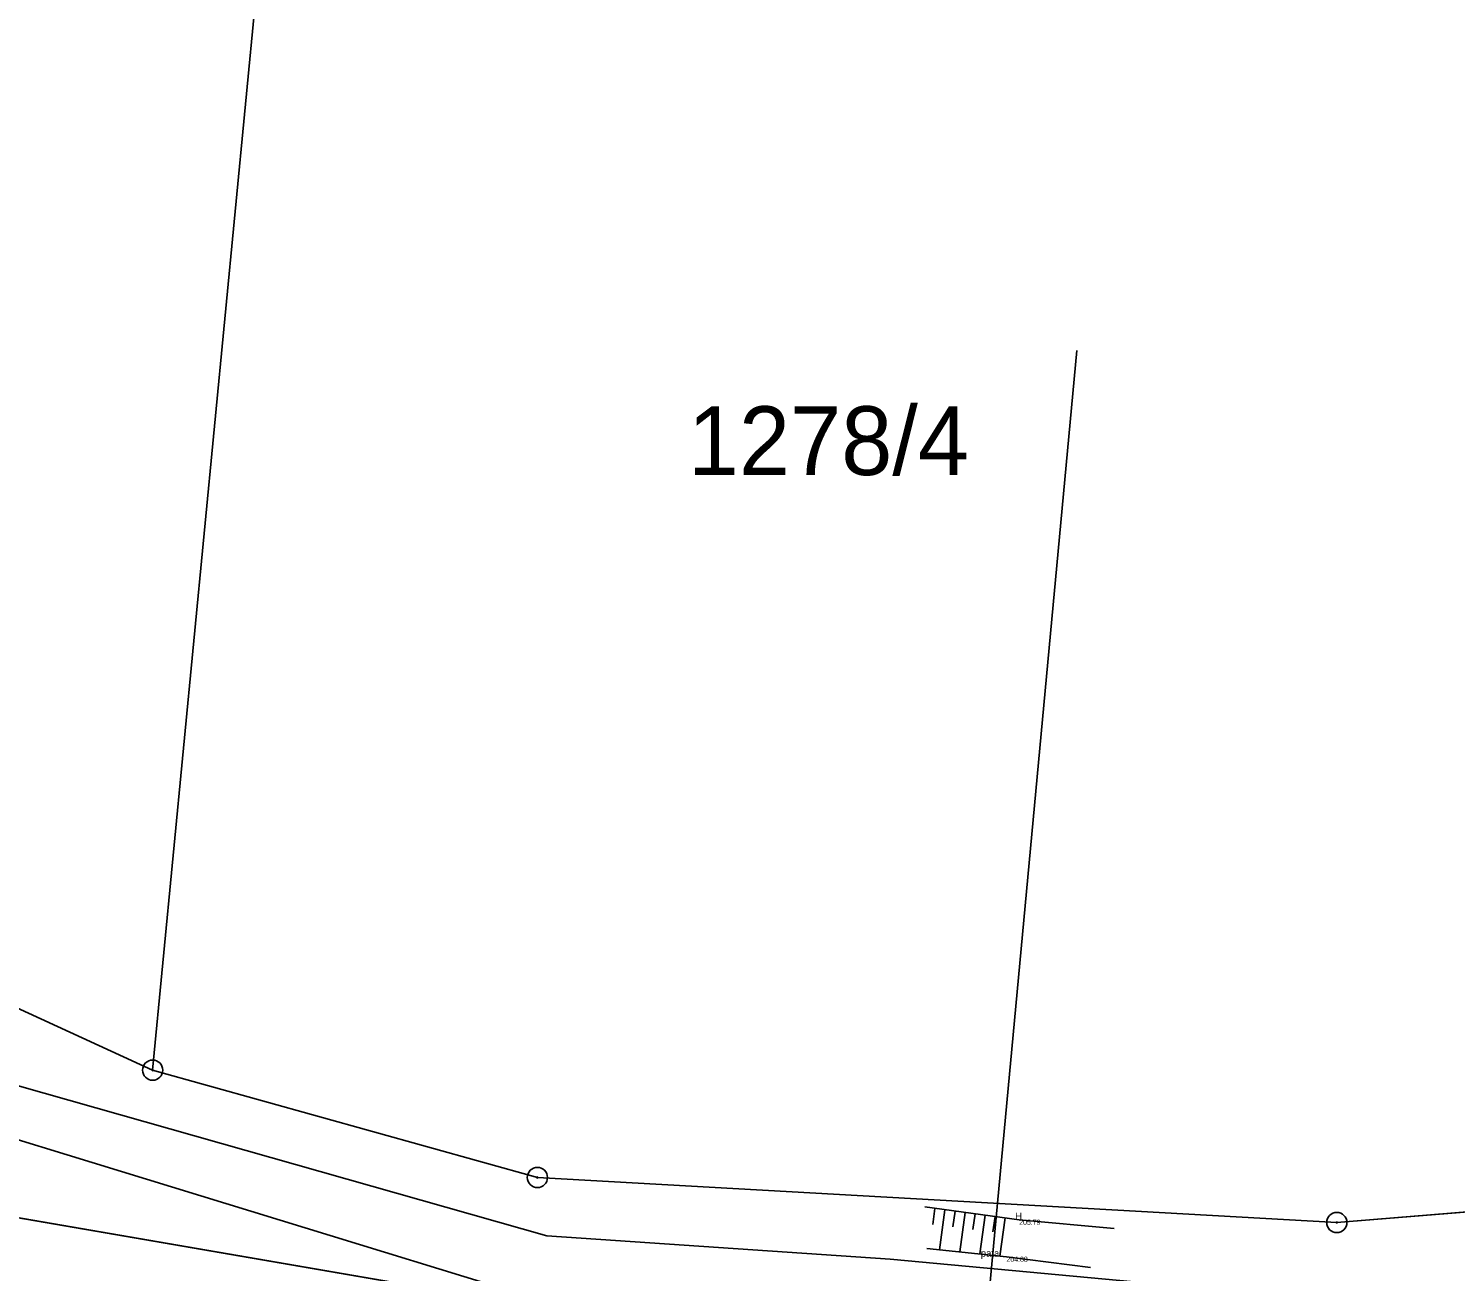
# Model space of a CAD drawing. Extents: x -537341 to -532984, y -1143469 to -1141314.
# Drawn here: x -535152.1 to -535081.5, y -1142823.6 to -1142762.2 of the extents above; entities that cross this region are included whole.
import ezdxf

# ---------------------------------------------------------------- set-up
doc = ezdxf.new("R2010")
doc.units = 0
for name, color, linetype in [('Hranice parcel', 7, 'Continuous'), ('parcelní_č_2000', 7, 'Continuous'), ('u_obec_Horní_Moš', 7, 'Continuous'), ('u_osa_toku', 7, 'Continuous'), ('u_pozemkový_úřad', 7, 'Continuous'), ('u_pricne', 7, 'Continuous'), ('U_SOUKROMÉ', 7, 'Continuous'), ('Značky bodu BP', 7, 'Continuous'), ('ˇ1', 7, 'Continuous'), ('ˇ12', 7, 'Continuous'), ('ˇ13', 7, 'Continuous'), ('ˇ18', 7, 'Continuous'), ('ˇ3', 7, 'Continuous')]:
    doc.layers.add(name, color=color, linetype=linetype)

msp = doc.modelspace()

# ---------------------------------------------------------------- linework, layer by layer
at = {"layer": 'Hranice parcel'}
msp.add_line((-535145.96, -1142813.69), (-535134.247, -1142691.905), dxfattribs=at)
for points in [[(-535145.96, -1142813.69), (-535169.91, -1142802.7), (-535192.81, -1142789.83), (-535204.32, -1142784.26), (-535252.88, -1142770.83), (-535272.1, -1142771.17), (-535285.84, -1142775.59)], [(-535405.82, -1142867.75), (-535312.5, -1142806.96), (-535286.28, -1142782.06), (-535276.92, -1142778.23), (-535253.61, -1142777.35), (-535211.35, -1142788.27), (-535160.74, -1142814.65), (-535123.95, -1142825.93)], [(-535123.95, -1142825.93), (-535162.05, -1142819.37), (-535213.73, -1142796.84), (-535250.05, -1142784.79), (-535271.96, -1142788.49), (-535310.42, -1142811.28), (-535403.84, -1142870.01)], [(-535070.92, -1142819.89), (-535087.39, -1142821.23), (-535126.93, -1142819), (-535145.96, -1142813.69)]]:
    msp.add_lwpolyline(points, dxfattribs=at)
at = {"layer": 'u_obec_Horní_Moš'}
for points in [[(-535145.96, -1142813.69), (-535169.91, -1142802.7), (-535192.81, -1142789.83), (-535204.32, -1142784.26), (-535252.88, -1142770.83), (-535272.1, -1142771.17), (-535285.84, -1142775.59)], [(-535405.82, -1142867.75), (-535312.5, -1142806.96), (-535286.28, -1142782.06), (-535276.92, -1142778.23), (-535253.61, -1142777.35), (-535211.35, -1142788.27), (-535160.74, -1142814.65), (-535123.95, -1142825.93)], [(-535070.92, -1142819.89), (-535087.39, -1142821.23), (-535126.93, -1142819), (-535145.96, -1142813.69)]]:
    msp.add_lwpolyline(points, dxfattribs=at)
at = {"layer": 'u_osa_toku'}
msp.add_lwpolyline([(-535260.582, -1142774.976), (-535252.427, -1142775.194), (-535238.285, -1142777.932), (-535206.255, -1142787.029), (-535160.007, -1142812.372), (-535126.471, -1142821.884), (-535109.48, -1142823.039), (-535088.356, -1142825.002), (-535065.679, -1142822.408), (-535055.402, -1142821.914), (-535044.659, -1142821.993), (-534991.553, -1142827.025), (-534966.505, -1142828.778), (-534955.891, -1142830.192), (-534942.11, -1142833.833), (-534919.335, -1142841.154), (-534875.463, -1142853.452), (-534792.866, -1142883.369), (-534735.912, -1142905.174), (-534690.752, -1142922.463), (-534647.384, -1142937.62), (-534638.575, -1142939.364), (-534623.017, -1142940.808), (-534607.282, -1142942.643)], dxfattribs=at)
at = {"layer": 'u_pozemkový_úřad'}
msp.add_line((-535123.95, -1142825.93), (-535162.05, -1142819.37), dxfattribs=at)
for points in [[(-535403.84, -1142870.01), (-535310.42, -1142811.28), (-535271.96, -1142788.49), (-535250.05, -1142784.79), (-535213.73, -1142796.84), (-535162.05, -1142819.37), (-535123.95, -1142825.93)], [(-535123.95, -1142825.93), (-535160.74, -1142814.65), (-535211.35, -1142788.27)]]:
    msp.add_lwpolyline(points, dxfattribs=at)
at = {"layer": 'u_pricne'}
msp.add_line((-535100.247, -1142778.083), (-535109.733, -1142880.122), dxfattribs=at)
at = {"layer": 'U_SOUKROMÉ'}
for p, q in [((-535134.247, -1142691.905), (-535145.96, -1142813.69)), ((-535145.96, -1142813.69), (-535134.247, -1142691.905)), ((-535145.96, -1142813.69), (-535126.93, -1142819)), ((-535126.93, -1142819), (-535087.39, -1142821.23)), ((-535087.39, -1142821.23), (-535070.92, -1142819.89))]:
    msp.add_line(p, q, dxfattribs=at)
msp.add_lwpolyline([(-535192.81, -1142789.83), (-535169.91, -1142802.7), (-535145.96, -1142813.69)], dxfattribs=at)
at = {"layer": 'Značky bodu BP'}
for centre, radius in [((-535145.96, -1142813.69), 0.5), ((-535145.96, -1142813.69), 0.0303), ((-535126.93, -1142819), 0.5), ((-535126.93, -1142819), 0.0303), ((-535087.39, -1142821.23), 0.5), ((-535087.39, -1142821.23), 0.0303)]:
    msp.add_circle(centre, radius, dxfattribs=at)
at = {"layer": 'ˇ1'}
for p, q in [((-535103.1, -1142821.09), (-535103.1, -1142821.09)), ((-535103.1, -1142821.09), (-535103.1, -1142821.09)), ((-535103.73, -1142822.92), (-535103.73, -1142822.92)), ((-535103.73, -1142822.92), (-535103.73, -1142822.92))]:
    msp.add_line(p, q, dxfattribs=at)
at = {"layer": 'ˇ12'}
for p, q in [((-535107.76, -1142820.46), (-535103.1, -1142821.09)), ((-535103.1, -1142821.09), (-535098.4, -1142821.53)), ((-535103.73, -1142822.92), (-535107.66, -1142822.52)), ((-535103.73, -1142822.92), (-535099.58, -1142823.45))]:
    msp.add_line(p, q, dxfattribs=at)
at = {"layer": 'ˇ13'}
for p, q in [((-535107.265, -1142820.527), (-535107.373, -1142821.329)), ((-535106.769, -1142820.594), (-535107.038, -1142822.583)), ((-535106.274, -1142820.661), (-535106.38, -1142821.45)), ((-535105.778, -1142820.728), (-535106.043, -1142822.685)), ((-535105.283, -1142820.795), (-535105.387, -1142821.571)), ((-535104.787, -1142820.862), (-535105.047, -1142822.786)), ((-535104.292, -1142820.929), (-535104.395, -1142821.692)), ((-535103.796, -1142820.996), (-535104.052, -1142822.887))]:
    msp.add_line(p, q, dxfattribs=at)

# ---------------------------------------------------------------- texts
at = {"layer": 'parcelní_č_2000'}
msp.add_text('1278/4', height=3.4, dxfattribs=at).set_placement((-535119.489, -1142784.252))
at = {"layer": 'ˇ18'}
for s, p in [('H', (-535103.298, -1142821.09)), ('pata', (-535104.997, -1142822.92))]:
    msp.add_text(s, height=0.35, dxfattribs=at).set_placement(p)
at = {"layer": 'ˇ3'}
for s, p in [('205.79 ', (-535103.1, -1142821.34)), ('204.88 ', (-535103.73, -1142823.17))]:
    msp.add_text(s, height=0.25, dxfattribs=at).set_placement(p)

doc.saveas('drawing.dxf')
